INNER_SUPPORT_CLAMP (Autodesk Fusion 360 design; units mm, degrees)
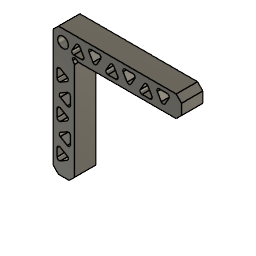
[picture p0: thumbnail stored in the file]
sketch "Sketch1" plane through (0, 0, 0) normal (0, 1, 0) x axis (1, 0, 0)
  line L1 (-76.2, 76.2) -> (-76.2, -76.2)
  line L2 (-50.8, 76.2) -> (-76.2, 76.2)
  line L3 (-50.8, -50.8) -> (-50.8, 76.2)
  line L4 (76.2, -50.8) -> (-50.8, -50.8)
  line L5 (76.2, -76.2) -> (76.2, -50.8)
  line L6 (-76.2, -76.2) -> (76.2, -76.2)
  line L7 (22.5, 0) -> (1.75, 0)
  line L8 (0, -22.5) -> (0, -1.75)
  point P2 (-76.2, -76.2)
  point P3 (-76.2, 76.2)
  point P6 (76.2, -50.8)
  point P7 (76.2, -76.2)
  vertical L1
  perpendicular L1 L2
  perpendicular L2 L3
  perpendicular L1 L4
  perpendicular L4 L5
  perpendicular L5 L6
  equal L1 L6
  equal L2 L5
  dimension "d1" distance P2 P3 = 152.4
  dimension "d2" distance P6 P7 = 25.4
extrude "Extrude1" new body sketch "Sketch1" profile of L1 L2 L3 L4 L5 L6 distance 25.4
sketch "Sketch2" plane through (0, -12.7, 0) normal (0, -1, 0) x axis (1, 0, 0)
  line L1 (76.2, 76.2) -> (76.2, 50.8)
  line L2 (-76.2, 76.2) -> (76.2, 76.2)
  line L3 (-76.2, -76.2) -> (-76.2, 76.2)
  line L4 (-50.8, -76.2) -> (-76.2, -76.2)
  line L5 (-50.8, 50.8) -> (-50.8, -76.2)
  line L6 (76.2, 50.8) -> (-50.8, 50.8)
  line L7 (-55.5625, -54.3346) -> (-71.4375, -63.5)
  line L8 (-71.4375, -45.1691) -> (-55.5625, -54.3346)
  line L9 (-71.4375, -63.5) -> (-71.4375, -45.1691)
  line L10 (-55.5625, -25.0052) -> (-55.5625, -43.336)
  line L11 (-71.4375, -34.1706) -> (-55.5625, -25.0052)
  line L12 (-55.5625, -43.336) -> (-71.4375, -34.1706)
  line L13 (-55.5625, -13.8533) -> (-71.4375, -23.0187)
  line L14 (-71.4375, -23.0187) -> (-71.4375, -4.6879)
  line L15 (-71.4375, -4.6879) -> (-55.5625, -13.8533)
  line L16 (-55.5625, -2.8548) -> (-71.4375, 6.3106)
  line L17 (-55.5625, 15.4761) -> (-55.5625, -2.8548)
  line L18 (-71.4375, 6.3106) -> (-55.5625, 15.4761)
  line L19 (-55.5625, 26.6279) -> (-71.4375, 17.4625)
  line L20 (-71.4375, 17.4625) -> (-71.4375, 35.7934)
  line L21 (-71.4375, 35.7934) -> (-55.5625, 26.6279)
  line L22 (63.5, 71.4375) -> (54.3346, 55.5625)
  line L23 (45.1691, 71.4375) -> (63.5, 71.4375)
  line L24 (54.3346, 55.5625) -> (45.1691, 71.4375)
  line L25 (43.336, 55.5625) -> (25.0052, 55.5625)
  line L26 (34.1706, 71.4375) -> (43.336, 55.5625)
  line L27 (25.0052, 55.5625) -> (34.1706, 71.4375)
  line L28 (23.0187, 71.4375) -> (13.8533, 55.5625)
  line L29 (4.6879, 71.4375) -> (23.0187, 71.4375)
  line L30 (13.8533, 55.5625) -> (4.6879, 71.4375)
  line L31 (2.8548, 55.5625) -> (-15.4761, 55.5625)
  line L32 (-6.3106, 71.4375) -> (2.8548, 55.5625)
  line L33 (-15.4761, 55.5625) -> (-6.3106, 71.4375)
  line L34 (-17.4625, 71.4375) -> (-26.6279, 55.5625)
  line L35 (-35.7934, 71.4375) -> (-17.4625, 71.4375)
  line L36 (-26.6279, 55.5625) -> (-35.7934, 71.4375)
  line L37 (-37.6265, 55.5625) -> (-55.9573, 55.5625)
  line L38 (-46.7919, 71.4375) -> (-37.6265, 55.5625)
  line L39 (-55.9573, 55.5625) -> (-46.7919, 71.4375)
  point P28 (45.1691, 71.4375)
  point P32 (34.1706, 71.4375)
  point P9 (-55.5625, -54.3346)
  point P8 (-71.4375, -63.5)
  point P14 (-71.4375, -34.1706)
  point P26 (63.5, 71.4375)
  point P30 (43.336, 55.5625)
  parallel L3 L9
  parallel L5 L10
  parallel L2 L23
  parallel L24 L26
  horizontal P28 P32
  dimension "d6" distance P9 L9 = 15.875
  dimension "d7" distance L3 L9 = 4.7625
  dimension "d8" distance L4 P8 = 12.7
  dimension "d9" distance P14 L10 = 15.875 (= "d6")
  dimension "d10" distance L5 L10 = 4.7625 (= "d7")
  dimension "d11" distance L8 L12 = 9.525
  dimension "d16" distance P26 L24 = 15.875
  dimension "d17" distance L2 L23 = 4.7625 (= "d7")
  dimension "d18" distance L1 P26 = 12.7 (= "d8")
  dimension "d19" distance P30 L27 = 15.875
  dimension "d20" distance L24 L26 = 9.525 (= "d11")
  dimension "d14" R-Pattern1-uDistance = -80.9625
  dimension "d15" R-Pattern1-vDistance = 0
  dimension "d23" R-Pattern2-uDistance = 80.9625
  dimension "d24" R-Pattern2-vDistance = 0
extrude "Extrude2" cut sketch "Sketch2" profile of L7 L8 L9 L10 L11 L12 L13 L14 L15 L16 L17 L18 L19 L20 L21 L22 L23 L24 L25 L26 L27 L28 L29 L30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 no distance stored
fillet "Fillet1" radius 2.54
sketch "Sketch3" plane through (0, -12.7, 0) normal (0, -1, 0) x axis (1, 0, 0)
  line L1 (-59.3725, -11.6536) -> (-67.6275, -6.8876)
  line L2 (-67.6275, -20.819) -> (-59.3725, -16.053)
  line L3 (-71.4375, -9.0873) -> (-71.4375, -18.6193)
  line L4 (31.9709, 67.6275) -> (27.2049, 59.3725)
  line L5 (41.1363, 59.3725) -> (36.3703, 67.6275)
  line L6 (29.4046, 55.5625) -> (38.9366, 55.5625)
  line L7 (-48.9916, 67.6275) -> (-53.7576, 59.3725)
  line L8 (-39.8262, 59.3725) -> (-44.5922, 67.6275)
  line L9 (-51.5579, 55.5625) -> (-42.0259, 55.5625)
  line L10 (6.8876, 67.6275) -> (11.6536, 59.3725)
  line L11 (18.6193, 71.4375) -> (9.0873, 71.4375)
  line L12 (16.053, 59.3725) -> (20.819, 67.6275)
  line L13 (-59.3725, 13.2764) -> (-67.6275, 8.5103)
  line L14 (-55.5625, 1.5446) -> (-55.5625, 11.0767)
  line L15 (-67.6275, 4.1109) -> (-59.3725, -0.6551)
  line L16 (-67.6275, -36.3703) -> (-59.3725, -41.1363)
  line L17 (-59.3725, -27.2049) -> (-67.6275, -31.9709)
  line L18 (-55.5625, -38.9366) -> (-55.5625, -29.4046)
  line L19 (47.3688, 67.6275) -> (52.1349, 59.3725)
  line L20 (59.1006, 71.4375) -> (49.5685, 71.4375)
  line L21 (56.5343, 59.3725) -> (61.3003, 67.6275)
  line L22 (-33.5937, 67.6275) -> (-28.8276, 59.3725)
  line L23 (-21.8619, 71.4375) -> (-31.394, 71.4375)
  line L24 (-24.4282, 59.3725) -> (-19.6622, 67.6275)
  line L25 (-8.5103, 67.6275) -> (-13.2764, 59.3725)
  line L26 (0.6551, 59.3725) -> (-4.1109, 67.6275)
  line L27 (-11.0767, 55.5625) -> (-1.5446, 55.5625)
  line L28 (-59.3725, 28.8276) -> (-67.6275, 33.5937)
  line L29 (-67.6275, 19.6622) -> (-59.3725, 24.4282)
  line L30 (-71.4375, 31.394) -> (-71.4375, 21.8619)
  line L31 (-71.4375, -49.5685) -> (-71.4375, -59.1006)
  line L32 (-59.3725, -52.1349) -> (-67.6275, -47.3688)
  line L33 (-67.6275, -61.3003) -> (-59.3725, -56.5343)
  line L34 (76.2, 76.2) -> (76.2, 50.8)
  line L35 (-76.2, 76.2) -> (76.2, 76.2)
  line L36 (-76.2, -76.2) -> (-76.2, 76.2)
  line L37 (-50.8, -76.2) -> (-76.2, -76.2)
  line L38 (-50.8, 50.8) -> (-50.8, -76.2)
  line L39 (76.2, 50.8) -> (-50.8, 50.8)
  arc A1 centre (-60.6425, -13.8533) radius 2.54 clockwise from (-59.3725, -11.6536) to (-59.3725, -16.053)
  arc A2 centre (-68.8975, -18.6193) radius 2.54 clockwise from (-67.6275, -20.819) to (-71.4375, -18.6193)
  arc A3 centre (-68.8975, -9.0873) radius 2.54 clockwise from (-71.4375, -9.0873) to (-67.6275, -6.8876)
  arc A4 centre (34.1706, 66.3575) radius 2.54 clockwise from (31.9709, 67.6275) to (36.3703, 67.6275)
  arc A5 centre (38.9366, 58.1025) radius 2.54 clockwise from (41.1363, 59.3725) to (38.9366, 55.5625)
  arc A6 centre (29.4046, 58.1025) radius 2.54 clockwise from (29.4046, 55.5625) to (27.2049, 59.3725)
  arc A7 centre (-46.7919, 66.3575) radius 2.54 clockwise from (-48.9916, 67.6275) to (-44.5922, 67.6275)
  arc A8 centre (-42.0259, 58.1025) radius 2.54 clockwise from (-39.8262, 59.3725) to (-42.0259, 55.5625)
  arc A9 centre (-51.5579, 58.1025) radius 2.54 clockwise from (-51.5579, 55.5625) to (-53.7576, 59.3725)
  arc A10 centre (9.0873, 68.8975) radius 2.54 clockwise from (6.8876, 67.6275) to (9.0873, 71.4375)
  arc A11 centre (18.6193, 68.8975) radius 2.54 clockwise from (18.6193, 71.4375) to (20.819, 67.6275)
  arc A12 centre (13.8533, 60.6425) radius 2.54 clockwise from (16.053, 59.3725) to (11.6536, 59.3725)
  arc A13 centre (-58.1025, 11.0767) radius 2.54 clockwise from (-59.3725, 13.2764) to (-55.5625, 11.0767)
  arc A14 centre (-58.1025, 1.5446) radius 2.54 clockwise from (-55.5625, 1.5446) to (-59.3725, -0.6551)
  arc A15 centre (-66.3575, 6.3106) radius 2.54 clockwise from (-67.6275, 4.1109) to (-67.6275, 8.5103)
  arc A16 centre (-66.3575, -34.1706) radius 2.54 clockwise from (-67.6275, -36.3703) to (-67.6275, -31.9709)
  arc A17 centre (-58.1025, -29.4046) radius 2.54 clockwise from (-59.3725, -27.2049) to (-55.5625, -29.4046)
  arc A18 centre (-58.1025, -38.9366) radius 2.54 clockwise from (-55.5625, -38.9366) to (-59.3725, -41.1363)
  arc A19 centre (49.5685, 68.8975) radius 2.54 clockwise from (47.3688, 67.6275) to (49.5685, 71.4375)
  arc A20 centre (59.1006, 68.8975) radius 2.54 clockwise from (59.1006, 71.4375) to (61.3003, 67.6275)
  arc A21 centre (54.3346, 60.6425) radius 2.54 clockwise from (56.5343, 59.3725) to (52.1349, 59.3725)
  arc A22 centre (-31.394, 68.8975) radius 2.54 clockwise from (-33.5937, 67.6275) to (-31.394, 71.4375)
  arc A23 centre (-21.8619, 68.8975) radius 2.54 clockwise from (-21.8619, 71.4375) to (-19.6622, 67.6275)
  arc A24 centre (-26.6279, 60.6425) radius 2.54 clockwise from (-24.4282, 59.3725) to (-28.8276, 59.3725)
  arc A25 centre (-6.3106, 66.3575) radius 2.54 clockwise from (-8.5103, 67.6275) to (-4.1109, 67.6275)
  arc A26 centre (-1.5446, 58.1025) radius 2.54 clockwise from (0.6551, 59.3725) to (-1.5446, 55.5625)
  arc A27 centre (-11.0767, 58.1025) radius 2.54 clockwise from (-11.0767, 55.5625) to (-13.2764, 59.3725)
  arc A28 centre (-60.6425, 26.6279) radius 2.54 clockwise from (-59.3725, 28.8276) to (-59.3725, 24.4282)
  arc A29 centre (-68.8975, 21.8619) radius 2.54 clockwise from (-67.6275, 19.6622) to (-71.4375, 21.8619)
  arc A30 centre (-68.8975, 31.394) radius 2.54 clockwise from (-71.4375, 31.394) to (-67.6275, 33.5937)
  arc A31 centre (-68.8975, -49.5685) radius 2.54 clockwise from (-71.4375, -49.5685) to (-67.6275, -47.3688)
  arc A32 centre (-60.6425, -54.3346) radius 2.54 clockwise from (-59.3725, -52.1349) to (-59.3725, -56.5343)
  arc A33 centre (-68.8975, -59.1006) radius 2.54 clockwise from (-67.6275, -61.3003) to (-71.4375, -59.1006)
  circle C1 centre (-50.8, 50.8) radius 2.3813
  point P106 (-50.8, 50.8)
  point P107 (-50.8, 50.8)
  coincident P106 P107
  dimension "d28" diameter C1 = 4.7625
extrude "Extrude3" cut sketch "Sketch3" profile of L38 L39 C1 no distance stored
chamfer "Chamfer1" distance 2.286
chamfer "Chamfer2" distance 6.35
sketch "Sketch4" plane through (0, -12.7, 0) normal (0, -1, 0) x axis (1, 0, 0)
  line L1 (-69.85, -76.2) -> (-76.2, -69.85)
  line L2 (-57.15, -76.2) -> (-69.85, -76.2)
  line L3 (-50.8, -69.85) -> (-57.15, -76.2)
  line L4 (-50.8, 46.1328) -> (-50.8, -69.85)
  line L5 (-52.8054, 49.516) -> (-50.8, 46.1328)
  line L6 (-46.1327, 50.8) -> (-49.516, 52.8054)
  line L7 (69.85, 50.8) -> (-46.1327, 50.8)
  line L8 (76.2, 57.15) -> (69.85, 50.8)
  line L9 (76.2, 69.85) -> (76.2, 57.15)
  line L10 (69.85, 76.2) -> (76.2, 69.85)
  line L11 (-69.85, 76.2) -> (69.85, 76.2)
  line L12 (-76.2, 69.85) -> (-69.85, 76.2)
  line L13 (-76.2, -69.85) -> (-76.2, 69.85)
  line L14 (-59.3725, -11.6536) -> (-67.6275, -6.8876)
  line L15 (-67.6275, -20.819) -> (-59.3725, -16.053)
  line L16 (-71.4375, -9.0873) -> (-71.4375, -18.6193)
  line L17 (31.9709, 67.6275) -> (27.2049, 59.3725)
  line L18 (41.1363, 59.3725) -> (36.3703, 67.6275)
  line L19 (29.4046, 55.5625) -> (38.9366, 55.5625)
  line L20 (-48.9916, 67.6275) -> (-53.7576, 59.3725)
  line L21 (-39.8262, 59.3725) -> (-44.5922, 67.6275)
  line L22 (-51.5579, 55.5625) -> (-42.0259, 55.5625)
  line L23 (6.8876, 67.6275) -> (11.6536, 59.3725)
  line L24 (18.6193, 71.4375) -> (9.0873, 71.4375)
  line L25 (16.053, 59.3725) -> (20.819, 67.6275)
  line L26 (-59.3725, 13.2764) -> (-67.6275, 8.5103)
  line L27 (-55.5625, 1.5446) -> (-55.5625, 11.0767)
  line L28 (-67.6275, 4.1109) -> (-59.3725, -0.6551)
  line L29 (-67.6275, -36.3703) -> (-59.3725, -41.1363)
  line L30 (-59.3725, -27.2049) -> (-67.6275, -31.9709)
  line L31 (-55.5625, -38.9366) -> (-55.5625, -29.4046)
  line L32 (47.3688, 67.6275) -> (52.1349, 59.3725)
  line L33 (59.1006, 71.4375) -> (49.5685, 71.4375)
  line L34 (56.5343, 59.3725) -> (61.3003, 67.6275)
  line L35 (-33.5937, 67.6275) -> (-28.8276, 59.3725)
  line L36 (-21.8619, 71.4375) -> (-31.394, 71.4375)
  line L37 (-24.4282, 59.3725) -> (-19.6622, 67.6275)
  line L38 (-8.5103, 67.6275) -> (-13.2764, 59.3725)
  line L39 (0.6551, 59.3725) -> (-4.1109, 67.6275)
  line L40 (-11.0767, 55.5625) -> (-1.5446, 55.5625)
  line L41 (-59.3725, 28.8276) -> (-67.6275, 33.5937)
  line L42 (-67.6275, 19.6622) -> (-59.3725, 24.4282)
  line L43 (-71.4375, 31.394) -> (-71.4375, 21.8619)
  line L44 (-71.4375, -49.5685) -> (-71.4375, -59.1006)
  line L45 (-59.3725, -52.1349) -> (-67.6275, -47.3688)
  line L46 (-67.6275, -61.3003) -> (-59.3725, -56.5343)
  arc A1 centre (-50.8, 50.8) radius 2.3812 clockwise from (-52.8054, 49.516) to (-49.516, 52.8054)
  arc A2 centre (-60.6425, -13.8533) radius 2.54 clockwise from (-59.3725, -11.6536) to (-59.3725, -16.053)
  arc A3 centre (-68.8975, -18.6193) radius 2.54 clockwise from (-67.6275, -20.819) to (-71.4375, -18.6193)
  arc A4 centre (-68.8975, -9.0873) radius 2.54 clockwise from (-71.4375, -9.0873) to (-67.6275, -6.8876)
  arc A5 centre (34.1706, 66.3575) radius 2.54 clockwise from (31.9709, 67.6275) to (36.3703, 67.6275)
  arc A6 centre (38.9366, 58.1025) radius 2.54 clockwise from (41.1363, 59.3725) to (38.9366, 55.5625)
  arc A7 centre (29.4046, 58.1025) radius 2.54 clockwise from (29.4046, 55.5625) to (27.2049, 59.3725)
  arc A8 centre (-46.7919, 66.3575) radius 2.54 clockwise from (-48.9916, 67.6275) to (-44.5922, 67.6275)
  arc A9 centre (-42.0259, 58.1025) radius 2.54 clockwise from (-39.8262, 59.3725) to (-42.0259, 55.5625)
  arc A10 centre (-51.5579, 58.1025) radius 2.54 clockwise from (-51.5579, 55.5625) to (-53.7576, 59.3725)
  arc A11 centre (9.0873, 68.8975) radius 2.54 clockwise from (6.8876, 67.6275) to (9.0873, 71.4375)
  arc A12 centre (18.6193, 68.8975) radius 2.54 clockwise from (18.6193, 71.4375) to (20.819, 67.6275)
  arc A13 centre (13.8533, 60.6425) radius 2.54 clockwise from (16.053, 59.3725) to (11.6536, 59.3725)
  arc A14 centre (-58.1025, 11.0767) radius 2.54 clockwise from (-59.3725, 13.2764) to (-55.5625, 11.0767)
  arc A15 centre (-58.1025, 1.5446) radius 2.54 clockwise from (-55.5625, 1.5446) to (-59.3725, -0.6551)
  arc A16 centre (-66.3575, 6.3106) radius 2.54 clockwise from (-67.6275, 4.1109) to (-67.6275, 8.5103)
  arc A17 centre (-66.3575, -34.1706) radius 2.54 clockwise from (-67.6275, -36.3703) to (-67.6275, -31.9709)
  arc A18 centre (-58.1025, -29.4046) radius 2.54 clockwise from (-59.3725, -27.2049) to (-55.5625, -29.4046)
  arc A19 centre (-58.1025, -38.9366) radius 2.54 clockwise from (-55.5625, -38.9366) to (-59.3725, -41.1363)
  arc A20 centre (49.5685, 68.8975) radius 2.54 clockwise from (47.3688, 67.6275) to (49.5685, 71.4375)
  arc A21 centre (59.1006, 68.8975) radius 2.54 clockwise from (59.1006, 71.4375) to (61.3003, 67.6275)
  arc A22 centre (54.3346, 60.6425) radius 2.54 clockwise from (56.5343, 59.3725) to (52.1349, 59.3725)
  arc A23 centre (-31.394, 68.8975) radius 2.54 clockwise from (-33.5937, 67.6275) to (-31.394, 71.4375)
  arc A24 centre (-21.8619, 68.8975) radius 2.54 clockwise from (-21.8619, 71.4375) to (-19.6622, 67.6275)
  arc A25 centre (-26.6279, 60.6425) radius 2.54 clockwise from (-24.4282, 59.3725) to (-28.8276, 59.3725)
  arc A26 centre (-6.3106, 66.3575) radius 2.54 clockwise from (-8.5103, 67.6275) to (-4.1109, 67.6275)
  arc A27 centre (-1.5446, 58.1025) radius 2.54 clockwise from (0.6551, 59.3725) to (-1.5446, 55.5625)
  arc A28 centre (-11.0767, 58.1025) radius 2.54 clockwise from (-11.0767, 55.5625) to (-13.2764, 59.3725)
  arc A29 centre (-60.6425, 26.6279) radius 2.54 clockwise from (-59.3725, 28.8276) to (-59.3725, 24.4282)
  arc A30 centre (-68.8975, 21.8619) radius 2.54 clockwise from (-67.6275, 19.6622) to (-71.4375, 21.8619)
  arc A31 centre (-68.8975, 31.394) radius 2.54 clockwise from (-71.4375, 31.394) to (-67.6275, 33.5937)
  arc A32 centre (-68.8975, -49.5685) radius 2.54 clockwise from (-71.4375, -49.5685) to (-67.6275, -47.3688)
  arc A33 centre (-60.6425, -54.3346) radius 2.54 clockwise from (-59.3725, -52.1349) to (-59.3725, -56.5343)
  arc A34 centre (-68.8975, -59.1006) radius 2.54 clockwise from (-67.6275, -61.3003) to (-71.4375, -59.1006)
  circle C1 centre (-64.3945, 62.1685) radius 6.35
  dimension "d32" diameter C1 = 12.7
extrude "Extrude4" cut sketch "Sketch4" profile of C1 no distance stored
